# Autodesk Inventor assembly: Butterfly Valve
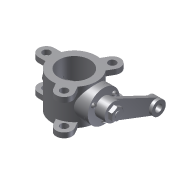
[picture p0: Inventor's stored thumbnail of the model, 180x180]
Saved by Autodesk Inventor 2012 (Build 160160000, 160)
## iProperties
Created: 2011-07
Part Number: Butterfly Valve
Document SubType Name: Assembly
Designer: CadCim
Author: CadCim
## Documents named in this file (8)
- C:\Users\CadCim\Documents\SAILESH\inventor-2011-fact-prt\c10-inv-2011-prt\c10_inv_2012_prt\Tutorials\c10_tut01_inv\Butterfly Valve\Butterfly Valve.iam
- C:\Users\CadCim\Documents\SAILESH\inventor-2011-fact-prt\c10-inv-2011-prt\c10_inv_2012_prt\Tutorials\c10_tut01_inv\Butterfly Valve\Body.ipt
- C:\Users\CadCim\Documents\SAILESH\inventor-2011-fact-prt\c10-inv-2011-prt\c10_inv_2012_prt\Tutorials\c10_tut01_inv\Butterfly Valve\Shaft.ipt
- C:\Users\CadCim\Documents\SAILESH\inventor-2011-fact-prt\c10-inv-2011-prt\c10_inv_2012_prt\Tutorials\c10_tut01_inv\Butterfly Valve\Retainer.ipt
- C:\Users\CadCim\Documents\SAILESH\inventor-2011-fact-prt\c10-inv-2011-prt\c10_inv_2012_prt\Tutorials\c10_tut01_inv\Butterfly Valve\Arm.ipt
- C:\Users\CadCim\Documents\SAILESH\inventor-2011-fact-prt\c10-inv-2011-prt\c10_inv_2012_prt\Tutorials\c10_tut01_inv\Butterfly Valve\Plate.ipt
- C:\Users\CadCim\Documents\SAILESH\inventor-2011-fact-prt\c10-inv-2011-prt\c10_inv_2012_prt\Tutorials\c10_tut01_inv\Butterfly Valve\Screw.ipt
- C:\Users\CadCim\Documents\SAILESH\inventor-2011-fact-prt\c10-inv-2011-prt\c10_inv_2012_prt\Tutorials\c10_tut01_inv\Butterfly Valve\Nut.ipt
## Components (10 placed, 7 different names)
1. Body:1 — Insert:1, Insert:2, Insert:3, Angle:1
2. Shaft:1 — Insert:1, Mate:1, Angle:1, Insert:5, Insert:6, Insert:10
3. Retainer:1 — Insert:2, Insert:3, Insert:4, Insert:7
4. Arm:1 — Insert:4, Mate:1
5. Plate:1 — Insert:5, Insert:6
6. Nut:1 — Insert:10
7. Screw:1 — Insert:7
8. Screw:2
9. Screw:3
10. Screw:4
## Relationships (10: Insert 8, Mate 1, Angle 1)
- Insert:1: Body:1 ↔ Shaft:1
- Insert:2: Body:1 ↔ Retainer:1
- Insert:3: Body:1 ↔ Retainer:1
- Insert:4: Retainer:1 ↔ Arm:1
- Mate:1: Shaft:1 ↔ Arm:1
- Angle:1: Body:1 ↔ Shaft:1
- Insert:5: Shaft:1 ↔ Plate:1
- Insert:6: Shaft:1 ↔ Plate:1
- Insert:7: Retainer:1 ↔ Screw:1
- Insert:10: Shaft:1 ↔ Nut:1
